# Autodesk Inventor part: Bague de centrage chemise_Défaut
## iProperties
Shininess: 64.0
Length Units: 11269
Angle Units: 11279
Time Units: 11290
Mass Units: 11283
Length Display Precision: 3
Angle Display Precision: 2
Compacted: True
Part Number: Bague de centrage chemise_Défaut
Document SubType Name: Modeling
Created: 2006-01
Material: Par défaut
Designer: riri
Density: 0.0
Volumn: 0.0
Area: 0.0
PropertySet Name: Model Information
Control State: 0
Master: False
Checked Out: False
Author: riri
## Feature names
1. Base1
